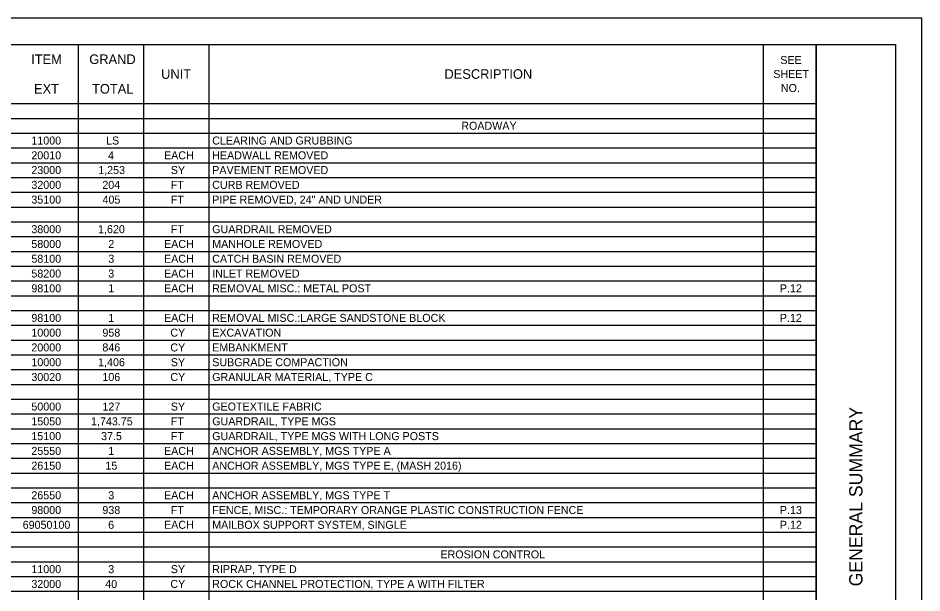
# Model space of a CAD drawing. Extents: x 0 to 34, y 0 to 22.
# Drawn here: x 16.9 to 34, y 11.11 to 22 of the extents above; entities that cross this region are included whole.
import ezdxf

# ---------------------------------------------------------------- set-up
doc = ezdxf.new("R2010")
doc.units = 0
for name, color, linetype in [('Default', 7, 'Continuous'), ('SH_Border', 7, 'Continuous'), ('SH_Cut_Line', 7, 'Continuous'), ('SH_Data', 7, 'Continuous')]:
    doc.layers.add(name, color=color, linetype=linetype)

msp = doc.modelspace()

# ---------------------------------------------------------------- linework, layer by layer
at = {"layer": 'Default'}
for p, q in [((1.5, 21.5), (32, 21.5)), ((18.035, 21.5), (18.035, 0.502)), ((19.27, 21.5), (19.27, 0.502)), ((20.505, 21.5), (20.505, 0.502)), ((30.995, 21.5), (30.995, 0.502)), ((32, 21.5), (32, 0.502)), ((1.5, 20.38), (32, 20.38)), ((1.5, 20.1), (32, 20.1)), ((1.5, 19.82), (32, 19.82)), ((1.5, 19.54), (32, 19.54)), ((1.5, 19.26), (32, 19.26)), ((1.5, 18.98), (32, 18.98)), ((1.5, 18.7), (32, 18.7)), ((1.5, 18.42), (32, 18.42)), ((1.5, 18.14), (32, 18.14)), ((1.5, 17.86), (32, 17.86)), ((1.5, 17.58), (32, 17.58)), ((1.5, 17.3), (32, 17.3)), ((1.5, 17.021), (32, 17.021)), ((1.5, 16.741), (32, 16.741)), ((1.5, 16.461), (32, 16.461)), ((1.5, 16.181), (32, 16.181)), ((1.5, 15.901), (32, 15.901)), ((1.5, 15.621), (32, 15.621)), ((1.5, 15.341), (32, 15.341)), ((1.5, 15.061), (32, 15.061)), ((1.5, 14.781), (32, 14.781)), ((1.5, 14.501), (32, 14.501)), ((1.5, 14.221), (32, 14.221)), ((1.5, 13.941), (32, 13.941)), ((1.5, 13.661), (32, 13.661)), ((1.5, 13.381), (32, 13.381)), ((1.5, 13.101), (32, 13.101)), ((1.5, 12.821), (32, 12.821)), ((1.5, 12.541), (32, 12.541)), ((1.5, 12.261), (32, 12.261)), ((1.5, 11.981), (32, 11.981)), ((1.5, 11.701), (32, 11.701)), ((1.5, 11.421), (32, 11.421)), ((1.5, 11.141), (32, 11.141))]:
    msp.add_line(p, q, dxfattribs=at)
at = {"layer": 'SH_Border'}
msp.add_line((32, 0.5), (32, 21.5), dxfattribs=at)
msp.add_lwpolyline([(1.5, 21.5), (33.5, 21.5), (33.5, 0.5), (1.5, 0.5)], close=True, dxfattribs=at)
at = {"layer": 'SH_Cut_Line'}
msp.add_lwpolyline([(0, 0), (34, 0), (34, 22), (0, 22)], close=True, dxfattribs=at)

# ---------------------------------------------------------------- texts
at = {"layer": 'Default'}
for s, height, p in [('ITEM', 0.1818, (17.145, 21.129)), ('GRAND', 0.1818, (18.245, 21.129)), ('SEE ', 0.1515, (31.32, 21.129)), ('UNIT', 0.1818, (19.604, 20.849)), ('DESCRIPTION', 0.18181, (24.965, 20.849)), ('SHEET ', 0.1515, (31.187, 20.864)), ('EXT', 0.1818, (17.199, 20.569)), ('TOTAL', 0.1818, (18.297, 20.569)), ('NO.', 0.1515, (31.331, 20.599)), ('ROADWAY', 0.1515, (25.284, 19.884)), ('11000', 0.1515, (17.149, 19.604)), ('LS', 0.1515, (18.562, 19.604)), ('CLEARING AND GRUBBING', 0.15151, (20.571, 19.604)), ('20010', 0.1515, (17.149, 19.324)), ('4', 0.152, (18.601, 19.324)), ('EACH', 0.1515, (19.659, 19.324)), ('HEADWALL REMOVED', 0.15151, (20.571, 19.324)), ('23000', 0.1515, (17.149, 19.045)), ('1,253', 0.1515, (18.414, 19.045)), ('SY', 0.1515, (19.788, 19.045)), ('PAVEMENT REMOVED', 0.15151, (20.571, 19.045)), ('32000', 0.1515, (17.149, 18.765)), ('204', 0.1515, (18.492, 18.765)), ('FT', 0.1515, (19.786, 18.765)), ('CURB REMOVED', 0.15151, (20.571, 18.765)), ('35100', 0.1515, (17.149, 18.485)), ('405', 0.1515, (18.495, 18.485)), ('FT', 0.1515, (19.786, 18.485)), ('PIPE REMOVED, 24" AND UNDER', 0.15151, (20.571, 18.485)), ('38000', 0.1515, (17.149, 17.925)), ('1,620', 0.1515, (18.411, 17.925)), ('FT', 0.1515, (19.786, 17.925)), ('GUARDRAIL REMOVED', 0.15151, (20.571, 17.925)), ('58000', 0.1515, (17.149, 17.645)), ('2', 0.152, (18.604, 17.645)), ('EACH', 0.1515, (19.659, 17.645)), ('MANHOLE REMOVED', 0.15151, (20.571, 17.645)), ('58100', 0.1515, (17.149, 17.365)), ('3', 0.152, (18.604, 17.365)), ('EACH', 0.1515, (19.659, 17.365)), ('CATCH BASIN REMOVED', 0.15151, (20.571, 17.365)), ('58200', 0.1515, (17.149, 17.085)), ('3', 0.152, (18.604, 17.085)), ('EACH', 0.1515, (19.659, 17.085)), ('INLET REMOVED', 0.15151, (20.571, 17.085)), ('98100', 0.1515, (17.149, 16.805)), ('1', 0.152, (18.604, 16.805)), ('EACH', 0.1515, (19.659, 16.805)), ('REMOVAL MISC.: METAL POST', 0.15151, (20.571, 16.805)), ('P.12', 0.1515, (31.312, 16.805)), ('98100', 0.1515, (17.149, 16.245)), ('1', 0.152, (18.604, 16.245)), ('EACH', 0.1515, (19.659, 16.245)), ('REMOVAL MISC.:LARGE SANDSTONE BLOCK', 0.15151, (20.571, 16.245)), ('P.12', 0.1515, (31.312, 16.245)), ('10000', 0.1515, (17.149, 15.965)), ('958', 0.1515, (18.493, 15.965)), ('CY', 0.1515, (19.779, 15.965)), ('EXCAVATION', 0.1515, (20.571, 15.965)), ('20000', 0.1515, (17.149, 15.685)), ('846', 0.1515, (18.493, 15.685)), ('CY', 0.1515, (19.779, 15.685)), ('EMBANKMENT', 0.1515, (20.571, 15.685)), ('10000', 0.1515, (17.149, 15.405)), ('1,406', 0.1515, (18.412, 15.405)), ('SY', 0.1515, (19.788, 15.405)), ('SUBGRADE COMPACTION', 0.15151, (20.571, 15.405)), ('30020', 0.1515, (17.149, 15.125)), ('106', 0.1515, (18.493, 15.125)), ('CY', 0.1515, (19.779, 15.125)), ('GRANULAR MATERIAL, TYPE C', 0.15151, (20.571, 15.125)), ('50000', 0.1515, (17.149, 14.565)), ('127', 0.1515, (18.494, 14.565)), ('SY', 0.1515, (19.788, 14.565)), ('GEOTEXTILE FABRIC', 0.15151, (20.571, 14.565)), ('15050', 0.1515, (17.149, 14.285)), ('1,743.75', 0.1515, (18.278, 14.285)), ('FT', 0.1515, (19.786, 14.285)), ('GUARDRAIL, TYPE MGS', 0.15151, (20.571, 14.285)), ('15100', 0.1515, (17.149, 14.005)), ('37.5', 0.1515, (18.468, 14.005)), ('FT', 0.1515, (19.786, 14.005)), ('GUARDRAIL, TYPE MGS WITH LONG POSTS', 0.15151, (20.571, 14.005)), ('25550', 0.1515, (17.149, 13.725)), ('1', 0.152, (18.604, 13.725)), ('EACH', 0.1515, (19.659, 13.725)), ('ANCHOR ASSEMBLY, MGS TYPE A', 0.15151, (20.571, 13.725)), ('26150', 0.1515, (17.149, 13.445)), ('15', 0.1515, (18.55, 13.445)), ('EACH', 0.1515, (19.659, 13.445)), ('ANCHOR ASSEMBLY, MGS TYPE E, (MASH 2016)', 0.15151, (20.571, 13.445)), ('26550', 0.1515, (17.149, 12.885)), ('3', 0.152, (18.604, 12.885)), ('EACH', 0.1515, (19.659, 12.885)), ('ANCHOR ASSEMBLY, MGS TYPE T', 0.15151, (20.571, 12.885)), ('98000', 0.1515, (17.149, 12.605)), ('938', 0.1515, (18.493, 12.605)), ('FT', 0.1515, (19.786, 12.605)), ('FENCE, MISC.: TEMPORARY ORANGE PLASTIC CONSTRUCTION FENCE', 0.15151, (20.571, 12.605)), ('P.13', 0.1515, (31.313, 12.605)), ('69050100', 0.1515, (16.985, 12.325)), ('6', 0.152, (18.602, 12.325)), ('EACH', 0.1515, (19.659, 12.325)), ('MAILBOX SUPPORT SYSTEM, SINGLE', 0.15151, (20.571, 12.325)), ('P.12', 0.1515, (31.312, 12.325)), ('EROSION CONTROL', 0.15151, (24.889, 11.765)), ('11000', 0.1515, (17.149, 11.485)), ('3', 0.152, (18.604, 11.485)), ('SY', 0.1515, (19.788, 11.485)), ('RIPRAP, TYPE D', 0.15151, (20.571, 11.485)), ('32000', 0.1515, (17.149, 11.205)), ('40', 0.1515, (18.547, 11.205)), ('CY', 0.1515, (19.779, 11.205)), ('ROCK CHANNEL PROTECTION, TYPE A WITH FILTER', 0.15151, (20.571, 11.205))]:
    msp.add_text(s, height=height, dxfattribs=at).set_placement(p)
at = {"layer": 'SH_Data'}
msp.add_text('GENERAL SUMMARY', height=0.25, rotation=90, dxfattribs=at).set_placement((32.875, 11.235))

doc.saveas('drawing.dxf')
